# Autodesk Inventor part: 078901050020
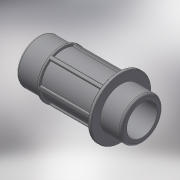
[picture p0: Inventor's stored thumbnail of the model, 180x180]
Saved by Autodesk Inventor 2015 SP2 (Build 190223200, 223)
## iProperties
Created: 2018-02
Part Number: 078901050020
Material: Generic
Description: PLASSON THREADED MALE ADAPTOR 50-2"
Document SubType Name: Modeling
Designer: KIM
Density: 1 g/cm^3
Appearance: Default
Author: KIM
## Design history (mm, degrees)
derived "078901.ipt"
feature "Solid1::078901.ipt"
tag "TaggingFeature1"
body "Solid1"
other parameters: "d4" = 2.9807, "d14" = 4.76912, "d15" = 2.38456, "d17" = 0, "d20" = 360 deg, "d40" = 27, "d41" = 59.614, "d45" = 65.5754, "d46" = 41.7298, "d47" = 2.7, "d77" = 107, "d85" = 0.59614, "d91" = 21.4, "d103" = 24.61, "d104" = 69, "d105" = 0.59614, "R_" = 59.614, "E_" = 69, "l_2" = 27, "l_" = 107
